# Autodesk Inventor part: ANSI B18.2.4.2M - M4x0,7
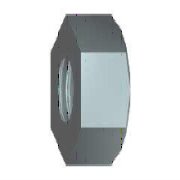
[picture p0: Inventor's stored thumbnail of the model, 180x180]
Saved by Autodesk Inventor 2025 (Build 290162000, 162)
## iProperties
Created: 2024-01
Part Number: ANSI B18.2.4.2M - M4x0,7
Material: Acciaio, Dolce
Description: Stili dadi esagonali metrici 2
Document SubType Name: Modeling
Standard: ANSI B18.2.4.2M
Designer: R5800u
Standard Revision: 2005
Standards Organization: ANSI
Language: it-IT
Size Designation: M4x0,7
Categories: <MemberInstance><Categories><Category DisplayName="Elementi di fissaggio" InternalName="e4da775c-781d-43d5-af7c-5136215cf5a6" Mnemonic="FSTN"><Category DisplayN
Density: 7.85 g/cm^3
Appearance: Semilucidato
IsCustomPart: 0
Author: R5800u
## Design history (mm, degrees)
node "MSC_A1"
node "MSC_PT1"
node "MSC_PT2"
node "MSC_PF1"
body "Solid1"
sketch "Schizzo1"
  geometry: L1 (3.5, 2.021)-(3.5, -2.021); L2 (3.5, -2.021)-(0, -4.041); L3 (0, -4.041)-(-3.5, -2.021); L4 (-3.5, -2.021)-(-3.5, 2.021); L5 (-3.5, 2.021)-(0, 4.041); L6 (0, 4.041)-(3.5, 2.021); C1 r 3.5 at (0, 0); 2 further points
  constraints: 12 end point, 2 coincident, 1 centre point, 1 tangent, 1 vertical, 11 other
  dimensions: "d0" = 7 diameter of C1 (= Smax)
extrude "Estrusione1" new body sketch "Schizzo1" distance "d1" = 3.8 (= Mmax); taper "d2" = 0 deg
sketch "Schizzo2"
  geometry: L1 (-3.5, 2.021)-(0, 4.041) reference; L2 (0, -4.041)-(-3.5, -2.021) reference; L3 (-3.5, 2.021)-(3.5, -2.021); L4 (-3.5, -2.021)-(3.5, 2.021); 1 further point
  constraints: 4 end point, 2 midpoint, 2 parallel
hole "Foro1" sketch "Schizzo2" diameter "d3" = 3.242; stored, may be unused: countersink angle "d7" = 90 deg, drill point angle "d9" = 118 deg; dims "d4" = 6, "d5" = 4, "d6" = 2, "d8" = 8
chamfer "Smusso1" distance "d10" = 0.35 (= 0.5 x PTC); stored, may be unused: second distance "d11" = 2, angle "d12" = 45 deg
revolve "Rivoluzione1" stored, may be unused: angle "d15" = 90 deg
sketch "Schizzo3"
  geometry: L1 (-7.017, 0)-(2.17, 0) reference; L2 (-5.705, 0)-(0.857, 0); L3 (-3.8, 0)-(-3.8, -4.041); L4 (-3.8, -4.041)-(0, -4.041); L5 (0, -4.041)-(0, 0); L6 (-3.8, -2.021)-(-3.8, -4.041) reference; L7 (0, -2.021)-(0, -4.041) reference; L8 (0, -4.041)-(-3.8, -4.041) reference; L9 (-3.8, -3.5)-(-3.487, -4.041); L10 (-3.8, -4.041)-(-3.8, -3.5); L11 (-3.8, -4.041)-(-3.487, -4.041); L12 (0, -3.5)-(-0.313, -4.041); L13 (-0.313, -4.041)-(0, -4.041); L14 (0, -4.041)-(0, -3.5)
  constraints: 21 end point, 6 point on line, 5 collinear, 4 vertical, 3 equal length, 2 horizontal
  dimensions: "d32" = 3.5 distance from line of L9.start L1 (= 0.5 x Smax); "d33" = 30 deg angle of L9 L3
other parameters: "NND" = 4 [user parameter; used in 1 equation term], "Smax" = 7 [user parameter; used in 2 equation terms], "Mmax" = 3.8 [user parameter; used in 1 equation term], "PTC" = 0.7 [user parameter; used in 1 equation term], "d16" = 0, "d17" = 0, "d18" = 0, "d19" = 0, "d21" = 0, "d22" = 0, "d23" = 0, "THREADDIA" = 4 (= NND) [user parameter], "TEMPLATE" = 12.345 [user parameter]
